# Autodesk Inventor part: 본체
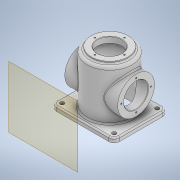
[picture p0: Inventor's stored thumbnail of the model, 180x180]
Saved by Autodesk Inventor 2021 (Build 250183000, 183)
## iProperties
Created: 2021-02
Part Number: 본체
Material: 알루미늄 6061
Document SubType Name: Modeling
Designer: 201-12
Density: 2.7 g/cm^3
Appearance: 기본값
Mass: 1235.61 g
Surface Area: 1069.52 cm^2
Volume: 457.635 cm^3
Author: 201-12
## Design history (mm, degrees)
sketch "스케치1"
  geometry: 1 further point
sketch "스케치2"
  geometry: L1 (70, -60)-(-70, -60); L2 (-70, -60)-(-70, 60); L3 (-70, 60)-(70, 60); L4 (70, 60)-(70, -60); L5 (70, -60)-(-70, 60); L6 (-70, -60)-(70, 60); 1 further point
  constraints: 12 end point, 2 midpoint, 2 parallel, 1 horizontal, 1 perpendicular
  dimensions: "d0" = 140 distance of L2.end L3.end; "d1" = 120 distance of L1.end L2.end
extrude "돌출1" new body sketch "스케치2" distance "d2" = 10; taper "d3" = 0 deg
sketch "스케치3"
  geometry: C1 r 50 at (0, 0); 1 further point
  constraints: 1 centre point, 1 coincident
  dimensions: "d4" = 100 diameter of C1
extrude "돌출2" join sketch "스케치3" distance "d5" = 110; taper "d6" = 0 deg
sketch "스케치4"
  geometry: C1 r 41 at (0, 0); 1 further point
  constraints: 1 centre point, 1 coincident
  dimensions: "d7" = 82 diameter of C1
extrude "돌출3" join sketch "스케치4" distance "d8" = 5; taper "d9" = 0 deg
sketch "스케치5"
  geometry: C1 r 41 at (0, 60); 1 further point
  constraints: 1 centre point, 1 vertical alignment
  dimensions: "d10" = 82 diameter of C1; "d11" = 60 distance of point (0, 0) C1.centre
extrude "돌출4" join sketch "스케치5" stored distance "d12" = 118; taper "d13" = 0 deg
sketch "스케치6"
  geometry: C1 r 41 at (0, 0) reference; 2 further points
  constraints: 1 coincident
hole "구멍1" sketch "스케치6" at (0, 0) diameter "d14" = 54; stored, may be unused: countersink angle "d18" = 90 deg, drill point angle "d20" = 0 deg; dims "d15" = 7, "d16" = 4, "d17" = 2, "d19" = 9
hole "구멍2" sketch "스케치1" diameter "d21" = 84; stored, may be unused: countersink angle "d25" = 90 deg, drill point angle "d27" = 0 deg; dims "d22" = 7, "d23" = 4, "d24" = 2, "d26" = 112
sketch "스케치7"
  geometry: 2 further points
  constraints: 1 coincident
hole "구멍3" sketch "스케치7" at (0, 0) diameter "d28" = 54; stored, may be unused: countersink angle "d32" = 90 deg, drill point angle "d34" = 0 deg; dims "d29" = 7, "d30" = 4, "d31" = 2, "d33" = 112
fillet "모깎기1" dims "d35" = 12
fillet "모깎기2" dims "d36" = 3
sketch "스케치8"
  geometry: A1 r 12 centre (-58, 48) between (-58, 60) and (-70, 48) reference; A2 r 12 centre (-58, -48) between (-70, -48) and (-58, -60) reference; A3 r 12 centre (58, -48) between (58, -60) and (70, -48) reference; A4 r 12 centre (58, 48) between (70, 48) and (58, 60) reference; 5 further points
  constraints: 4 coincident
hole "구멍4" sketch "스케치8" at (-58, 48), (-58, -48), (58, -48), (58, 48) diameter "d37" = 9; stored, may be unused: countersink angle "d41" = 90 deg, drill point angle "d43" = 0 deg; dims "d38" = 7, "d39" = 4, "d40" = 2, "d42" = 112
sketch "스케치9"
  geometry: L1 (-60, -60)-(-60, -60) reference; A1 r 33 centre (0, 0) between (0, 33) and (33, 0); 4 further points
  constraints: 4 point on circle, 1 centre point, 1 point on line, 1 vertical alignment
  dimensions: "d44" = 66 diameter of A1; "d45" = 60 distance from line of L1 A1.centre
sketch "스케치10"
  geometry: 1 further point
hole "구멍5" sketch "스케치9" diameter "d46" = 3.242; stored, may be unused: countersink angle "d50" = 90 deg, drill point angle "d52" = 118 deg; dims "d47" = 8, "d48" = 4, "d49" = 2, "d51" = 10
sketch "스케치11"
  geometry: A1 r 33 centre (0, 0) between (-33, 0) and (0, -33); 3 further points
  constraints: 4 point on circle, 1 centre point, 1 coincident
  dimensions: "d53" = 66 diameter of A1
hole "구멍6" sketch "스케치11" at (0, -33), (-33, 0), (0, 33), (33, 0) diameter "d54" = 3.242; stored, may be unused: countersink angle "d58" = 90 deg, drill point angle "d60" = 118 deg; dims "d55" = 8, "d56" = 4, "d57" = 2, "d59" = 10
chamfer "모따기1" distance "d61" = 1; stored, may be unused: second distance "d62" = 2, angle "d63" = 45 deg
chamfer "모따기2" distance "d64" = 1; stored, may be unused: second distance "d65" = 2, angle "d66" = 45 deg
fillet "모깎기3" dims "d67" = 6
fillet "모깎기4" dims "d68" = 3
fillet "모깎기5" dims "d69" = 3
fillet "모깎기6" dims "d70" = 3
node "작업 평면2"
sketch "스케치13"
  geometry: 2 further points
  constraints: 1 vertical alignment, 1 other
  dimensions: "d84" = 66 distance of point (0, 0) point (0, 66)
feature "엠보싱1" sketch "스케치13" dims "d11" = 60, "d73" = 1, "d74" = 0
sketch "스케치14"
  geometry: L1 (-48, -60)-(48, -60) reference; C1 r 33 at (0, 0); C2 r 1.621 at (0, 33) reference; C3 r 1.621 at (-33, 0) reference; C4 r 1.621 at (0, -33) reference; C5 r 1.621 at (33, 0) reference; 6 further points
  constraints: 4 coincident, 1 centre point, 1 midpoint, 1 vertical alignment
  dimensions: "d75" = 66 diameter of C1; "d76" = 60 distance from line of L1 C1.centre
hole "구멍7" sketch "스케치14" at (0, 33), (-33, 0), (0, -33), (33, 0) diameter "d77" = 3.242; stored, may be unused: countersink angle "d81" = 90 deg, drill point angle "d83" = 118 deg; dims "d78" = 8, "d79" = 4, "d80" = 2, "d82" = 10
node "솔리드1"
mirror "미러1"
node "투영된 루프1"
feature "A9D066F2-1C7D-4E18-AEED-F7BC21143FA4" dims "d14" = 54, "d15" = 7, "d16" = 4, "d17" = 2, "d18" = 90 deg, "d19" = 9, "d20" = 0
other parameters: "d72" = 147.6375
